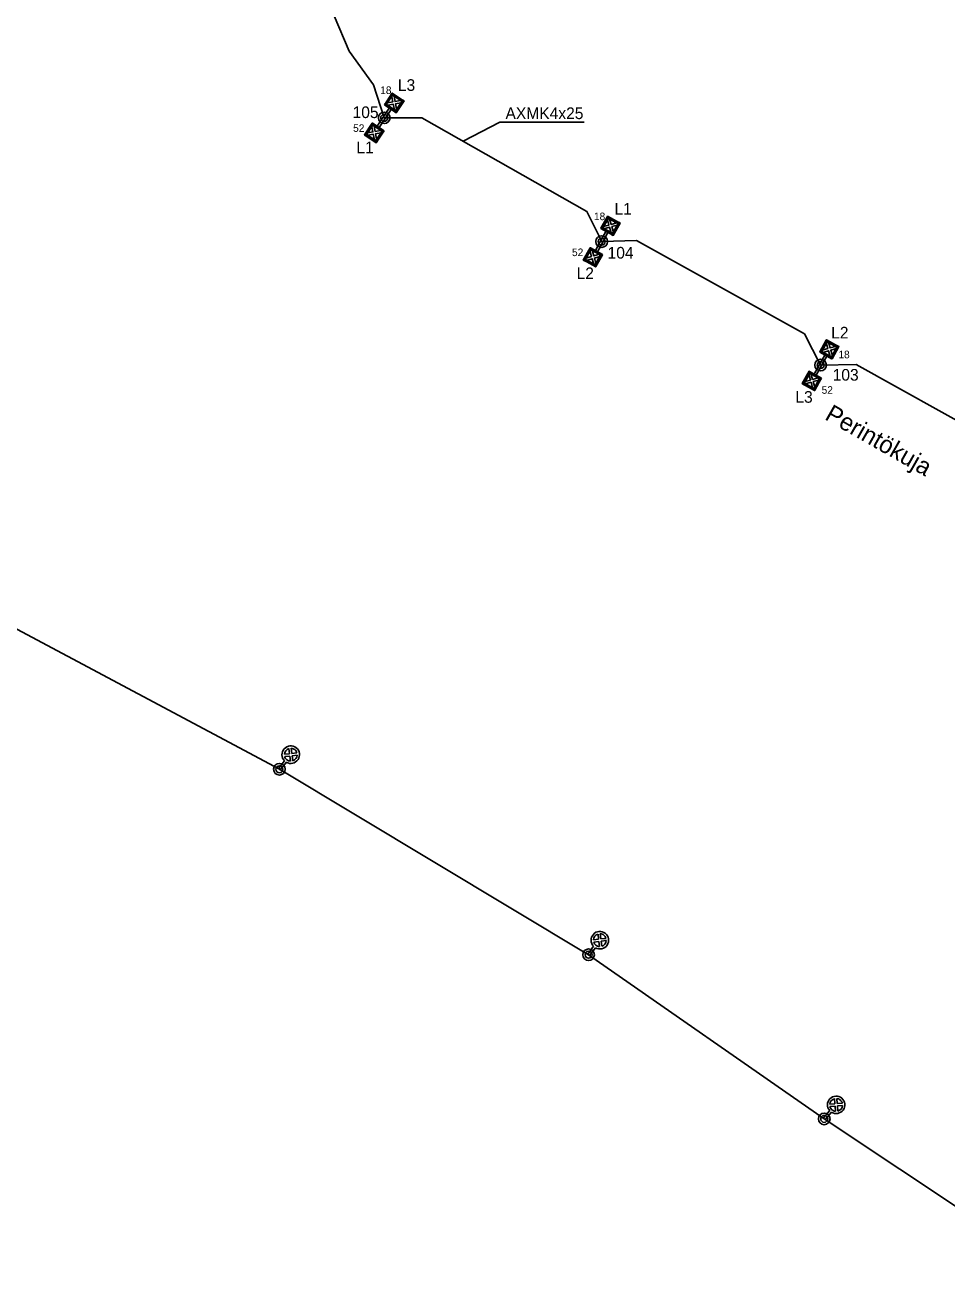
# Model space of a CAD drawing. Extents: x 25497852 to 25498297, y 6686544 to 6687252.
# Drawn here: x 25498074.6 to 25498193.2, y 6686900.1 to 6687062.7 of the extents above; entities that cross this region are included whole.
import ezdxf

# ---------------------------------------------------------------- set-up
doc = ezdxf.new("R2010")
doc.units = 0
for name, color, linetype in [('KayttoOikeusYksikko_piste_tunnus', 7, 'Continuous'), ('KiinteistoNimi', 7, 'Continuous'), ('Rasitealue', 7, 'Continuous'), ('Rasiteviiva', 7, 'Continuous'), ('Taso 1', 7, 'Continuous')]:
    doc.layers.add(name, color=color, linetype=linetype)

msp = doc.modelspace()

# ---------------------------------------------------------------- linework, layer by layer
at = {"layer": 'KayttoOikeusYksikko_piste_tunnus'}
for p, q in [((25498108.58, 6686968.85), (25498107.92, 6686968.77)), ((25498107.96, 6686968.47), (25498108.61, 6686968.55)), ((25498108.5, 6686969.51), (25498108.58, 6686968.85)), ((25498108.61, 6686968.55), (25498108.69, 6686967.9)), ((25498108.87, 6686968.89), (25498108.79, 6686969.55)), ((25498109.53, 6686968.97), (25498108.87, 6686968.89)), ((25498108.91, 6686968.59), (25498109.57, 6686968.67)), ((25498108.99, 6686967.93), (25498108.91, 6686968.59)), ((25498107.17, 6686966.95), (25498107.94, 6686967.94)), ((25498107.4, 6686966.76), (25498107.17, 6686966.95)), ((25498108.18, 6686967.75), (25498107.4, 6686966.76)), ((25498148.29, 6686945.61), (25498148.37, 6686944.96)), ((25498148.66, 6686944.99), (25498148.58, 6686945.65)), ((25498146.96, 6686943.05), (25498147.73, 6686944.04)), ((25498147.97, 6686943.86), (25498147.19, 6686942.87)), ((25498148.37, 6686944.96), (25498147.71, 6686944.88)), ((25498147.75, 6686944.58), (25498148.4, 6686944.66)), ((25498148.4, 6686944.66), (25498148.48, 6686944)), ((25498149.32, 6686945.07), (25498148.66, 6686944.99)), ((25498148.7, 6686944.7), (25498149.36, 6686944.78)), ((25498148.78, 6686944.04), (25498148.7, 6686944.7)), ((25498147.19, 6686942.87), (25498146.96, 6686943.05)), ((25498178.72, 6686924.42), (25498178.78, 6686923.76)), ((25498179.08, 6686923.78), (25498179.02, 6686924.44)), ((25498177.29, 6686921.91), (25498178.1, 6686922.87)), ((25498178.33, 6686922.67), (25498177.52, 6686921.72)), ((25498178.78, 6686923.76), (25498178.12, 6686923.71)), ((25498178.14, 6686923.41), (25498178.8, 6686923.46)), ((25498178.8, 6686923.46), (25498178.85, 6686922.8)), ((25498179.74, 6686923.83), (25498179.08, 6686923.78)), ((25498179.1, 6686923.48), (25498179.76, 6686923.54)), ((25498179.15, 6686922.82), (25498179.1, 6686923.48)), ((25498177.52, 6686921.72), (25498177.29, 6686921.91))]:
    msp.add_line(p, q, dxfattribs=at)
for points in [[(25498121.77, 6687053.89), (25498120.83, 6687052.47), (25498120.99, 6687052.36), (25498121.94, 6687053.78)], [(25498122.12, 6687051.61), (25498121.94, 6687052.5), (25498121.06, 6687052.32), (25498120.88, 6687052.44), (25498121, 6687052.62), (25498121.88, 6687052.79), (25498121.7, 6687053.68), (25498121.82, 6687053.86), (25498122, 6687053.74), (25498122.18, 6687052.85), (25498123.06, 6687053.03), (25498123.24, 6687052.91), (25498123.12, 6687052.74), (25498122.24, 6687052.56), (25498122.41, 6687051.67), (25498122.3, 6687051.5)], [(25498123.16, 6687052.8), (25498123.27, 6687052.96), (25498121.8, 6687053.94), (25498121.69, 6687053.77)], [(25498122.15, 6687051.52), (25498123.16, 6687053.04), (25498123.32, 6687052.93), (25498122.31, 6687051.41)], [(25498120.65, 6687050.83), (25498121.43, 6687052), (25498121.68, 6687051.83), (25498120.9, 6687050.66)], [(25498120.79, 6687052.42), (25498120.9, 6687052.59), (25498122.37, 6687051.61), (25498122.26, 6687051.45)], [(25498119.4, 6687049.97), (25498118.39, 6687048.45), (25498118.22, 6687048.56), (25498119.23, 6687050.08)], [(25498119.43, 6687049.88), (25498119.61, 6687048.99), (25498120.49, 6687049.17), (25498120.67, 6687049.05), (25498120.55, 6687048.88), (25498119.67, 6687048.7), (25498119.84, 6687047.81), (25498119.73, 6687047.64), (25498119.55, 6687047.75), (25498119.37, 6687048.64), (25498118.49, 6687048.46), (25498118.31, 6687048.58), (25498118.43, 6687048.76), (25498119.31, 6687048.93), (25498119.13, 6687049.82), (25498119.25, 6687050)], [(25498120.75, 6687049.07), (25498120.64, 6687048.9), (25498119.17, 6687049.88), (25498119.28, 6687050.05)], [(25498120.9, 6687050.66), (25498120.12, 6687049.49), (25498119.87, 6687049.66), (25498120.65, 6687050.83)], [(25498118.39, 6687048.69), (25498118.27, 6687048.53), (25498119.74, 6687047.55), (25498119.85, 6687047.72)], [(25498119.78, 6687047.6), (25498120.72, 6687049.02), (25498120.55, 6687049.13), (25498119.61, 6687047.71)], [(25498150.97, 6687037.05), (25498151.07, 6687037.22), (25498149.53, 6687038.08), (25498149.43, 6687037.9)], [(25498148.64, 6687036.48), (25498148.74, 6687036.66), (25498150.28, 6687035.8), (25498150.19, 6687035.63)], [(25498149.5, 6687038.03), (25498148.67, 6687036.54), (25498148.85, 6687036.44), (25498149.67, 6687037.93)], [(25498150.03, 6687035.79), (25498149.78, 6687036.65), (25498148.91, 6687036.41), (25498148.73, 6687036.51), (25498148.83, 6687036.69), (25498149.7, 6687036.94), (25498149.45, 6687037.81), (25498149.55, 6687038), (25498149.74, 6687037.89), (25498149.99, 6687037.02), (25498150.86, 6687037.27), (25498151.04, 6687037.17), (25498150.94, 6687036.98), (25498150.07, 6687036.74), (25498150.32, 6687035.87), (25498150.22, 6687035.68)], [(25498150.07, 6687035.7), (25498150.95, 6687037.29), (25498151.12, 6687037.19), (25498150.24, 6687035.6)], [(25498148.89, 6687034.74), (25498148.21, 6687033.51), (25498147.95, 6687033.65), (25498148.63, 6687034.88)], [(25498148.63, 6687034.88), (25498149.31, 6687036.12), (25498149.57, 6687035.97), (25498148.89, 6687034.74)], [(25498147.45, 6687033.93), (25498146.57, 6687032.33), (25498146.4, 6687032.43), (25498147.28, 6687034.02)], [(25498147.49, 6687033.84), (25498147.74, 6687032.97), (25498148.61, 6687033.22), (25498148.79, 6687033.12), (25498148.69, 6687032.93), (25498147.82, 6687032.68), (25498148.07, 6687031.81), (25498147.97, 6687031.63), (25498147.78, 6687031.73), (25498147.53, 6687032.6), (25498146.66, 6687032.35), (25498146.48, 6687032.45), (25498146.58, 6687032.64), (25498147.45, 6687032.89), (25498147.2, 6687033.76), (25498147.3, 6687033.94)], [(25498148.88, 6687033.14), (25498148.78, 6687032.96), (25498147.24, 6687033.82), (25498147.33, 6687033.99)], [(25498148.02, 6687031.6), (25498148.85, 6687033.09), (25498148.67, 6687033.18), (25498147.85, 6687031.7)], [(25498146.55, 6687032.57), (25498146.45, 6687032.4), (25498147.99, 6687031.54), (25498148.09, 6687031.72)], [(25498177.67, 6687022.11), (25498176.85, 6687020.63), (25498177.02, 6687020.53), (25498177.85, 6687022.02)], [(25498178.21, 6687019.87), (25498177.96, 6687020.74), (25498177.09, 6687020.49), (25498176.9, 6687020.6), (25498177.01, 6687020.78), (25498177.87, 6687021.03), (25498177.63, 6687021.9), (25498177.73, 6687022.08), (25498177.91, 6687021.98), (25498178.16, 6687021.11), (25498179.03, 6687021.36), (25498179.22, 6687021.26), (25498179.11, 6687021.07), (25498178.25, 6687020.82), (25498178.5, 6687019.96), (25498178.39, 6687019.77)], [(25498179.15, 6687021.14), (25498179.25, 6687021.31), (25498177.7, 6687022.17), (25498177.61, 6687021.99)], [(25498176.8, 6687018.97), (25498177.49, 6687020.2), (25498177.75, 6687020.06), (25498177.07, 6687018.83)], [(25498176.82, 6687020.57), (25498176.92, 6687020.75), (25498178.46, 6687019.89), (25498178.36, 6687019.72)], [(25498178.24, 6687019.79), (25498179.12, 6687021.38), (25498179.3, 6687021.28), (25498178.42, 6687019.69)], [(25498177.07, 6687018.83), (25498176.38, 6687017.6), (25498176.12, 6687017.74), (25498176.8, 6687018.97)], [(25498175.63, 6687018.01), (25498174.75, 6687016.42), (25498174.57, 6687016.52), (25498175.45, 6687018.11)], [(25498175.66, 6687017.93), (25498175.91, 6687017.06), (25498176.78, 6687017.31), (25498176.97, 6687017.2), (25498176.86, 6687017.02), (25498176, 6687016.77), (25498176.25, 6687015.9), (25498176.14, 6687015.72), (25498175.96, 6687015.82), (25498175.71, 6687016.69), (25498174.84, 6687016.44), (25498174.65, 6687016.54), (25498174.76, 6687016.73), (25498175.62, 6687016.98), (25498175.37, 6687017.84), (25498175.48, 6687018.03)], [(25498177.05, 6687017.23), (25498176.95, 6687017.05), (25498175.41, 6687017.91), (25498175.51, 6687018.08)], [(25498176.2, 6687015.69), (25498177.02, 6687017.17), (25498176.85, 6687017.27), (25498176.02, 6687015.78)], [(25498174.72, 6687016.66), (25498174.62, 6687016.49), (25498176.17, 6687015.63), (25498176.26, 6687015.81)]]:
    msp.add_lwpolyline(points, close=True, dxfattribs=at)
for centre, radius, start, end in [((25498108.74, 6686968.72), 1.13, 52.004, 224.3417), ((25498108.74, 6686968.72), 0.825, 107.4797, 176.5283), ((25498108.74, 6686968.72), 0.825, 197.4797, 232.004), ((25498108.74, 6686968.72), 1.13, 239.6662, 52.004), ((25498108.74, 6686968.72), 0.825, 52.004, 86.5283), ((25498108.74, 6686968.72), 0.825, 287.4797, 356.5283), ((25498108.74, 6686968.72), 0.825, 17.4797, 52.004), ((25498108.74, 6686968.72), 0.825, 232.004, 266.5283), ((25498148.53, 6686944.83), 1.13, 52.004, 224.3417), ((25498148.53, 6686944.83), 0.825, 107.4797, 176.5283), ((25498148.53, 6686944.83), 1.13, 239.6662, 52.004), ((25498148.53, 6686944.83), 0.825, 52.004, 86.5283), ((25498148.53, 6686944.83), 0.825, 17.4797, 52.004), ((25498148.53, 6686944.83), 0.825, 197.4797, 232.004), ((25498148.53, 6686944.83), 0.825, 232.004, 266.5283), ((25498148.53, 6686944.83), 0.825, 287.4797, 356.5283), ((25498178.94, 6686923.62), 1.12, 49.5556, 221.8933), ((25498178.94, 6686923.62), 0.825, 105.0313, 174.0799), ((25498178.94, 6686923.62), 1.12, 237.2178, 49.5556), ((25498178.94, 6686923.62), 0.825, 49.5556, 84.0799), ((25498178.94, 6686923.62), 0.825, 15.0313, 49.5556), ((25498178.94, 6686923.62), 0.825, 195.0313, 229.5556), ((25498178.94, 6686923.62), 0.825, 229.5556, 264.0799), ((25498178.94, 6686923.62), 0.825, 285.0313, 354.0799)]:
    msp.add_arc(centre, radius, start, end, dxfattribs=at)
at = {"layer": 'KiinteistoNimi'}
for centre, radius in [((25498120.77, 6687050.75), 0.75), ((25498120.77, 6687050.75), 0.45), ((25498148.76, 6687034.81), 0.75), ((25498148.76, 6687034.81), 0.45), ((25498176.94, 6687018.9), 0.75), ((25498176.94, 6687018.9), 0.45), ((25498107.28, 6686966.85), 0.75), ((25498107.28, 6686966.85), 0.75), ((25498107.28, 6686966.85), 0.45), ((25498107.28, 6686966.85), 0.45), ((25498147.08, 6686942.96), 0.75), ((25498147.08, 6686942.96), 0.45), ((25498177.4, 6686921.82), 0.75), ((25498177.4, 6686921.82), 0.45)]:
    msp.add_circle(centre, radius, dxfattribs=at)
at = {"layer": 'Rasitealue'}
for p, q in [((25498067.85, 6686987.87), (25498107.28, 6686966.85)), ((25498107.28, 6686966.85), (25498147.08, 6686942.96)), ((25498147.08, 6686942.96), (25498177.4, 6686921.82)), ((25498177.4, 6686921.82), (25498209.99, 6686900.07))]:
    msp.add_line(p, q, dxfattribs=at)
for points in [[(25498120.77, 6687050.75), (25498119.4, 6687055), (25498116.27, 6687059.35), (25498114.33, 6687063.87), (25498113.44, 6687067.35), (25498110.69, 6687070.16)], [(25498148.76, 6687034.81), (25498146.87, 6687038.69), (25498125.62, 6687050.76), (25498120.77, 6687050.75)], [(25498176.94, 6687018.9), (25498174.85, 6687022.93), (25498153.23, 6687034.97), (25498148.76, 6687034.81)], [(25498200.27, 6687005.75), (25498197.85, 6687009.86), (25498181.51, 6687018.98), (25498176.94, 6687018.9)]]:
    msp.add_lwpolyline(points, dxfattribs=at)
at = {"layer": 'Taso 1'}
msp.add_lwpolyline([(25498146.51, 6687050.2), (25498135.64, 6687050.2), (25498130.94, 6687047.74)], dxfattribs=at)

# ---------------------------------------------------------------- texts
at = {"layer": 'Rasiteviiva'}
for s, height, p in [('18', 0.975, (25498120.26, 6687053.82)), ('L3', 1.5, (25498122.53, 6687054.22)), ('105', 1.5, (25498116.7, 6687050.72)), ('AXMK4x25', 1.5, (25498136.38, 6687050.59)), ('52', 0.975, (25498116.77, 6687048.94)), ('L1', 1.5, (25498117.19, 6687046.19)), ('L1', 1.5, (25498150.41, 6687038.29)), ('18', 0.975, (25498147.77, 6687037.57)), ('52', 0.975, (25498144.94, 6687032.94)), ('104', 1.5, (25498149.52, 6687032.62)), ('L2', 1.5, (25498145.53, 6687029.98)), ('L2', 1.5, (25498178.3, 6687022.33)), ('18', 0.975, (25498179.23, 6687019.78)), ('103', 1.5, (25498178.49, 6687016.9)), ('L3', 1.5, (25498173.69, 6687014.05)), ('52', 0.975, (25498177.07, 6687015.21))]:
    msp.add_text(s, height=height, dxfattribs=at).set_placement(p)
msp.add_text('Perintökuja', height=2.25, rotation=330.3502, dxfattribs=at).set_placement((25498177.35, 6687011.98))

doc.saveas('drawing.dxf')
